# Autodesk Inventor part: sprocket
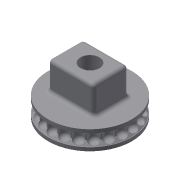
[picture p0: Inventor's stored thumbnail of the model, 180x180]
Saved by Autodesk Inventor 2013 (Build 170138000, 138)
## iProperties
Created: 2013-11
Part Number: sprocket
Material: Generic
Document SubType Name: Modeling
Designer: Jonas
Density: 1 g/cm^3
Author: Jonas
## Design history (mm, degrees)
sketch "Sketch1"
  geometry: C1 r 10.789 at (0, 0); 1 further point
  constraints: 1 centre point, 1 coincident
  dimensions: "d0" = 21.57743 diameter of C1 (computed from sprocket_N, pi)
extrude "Extrusion1" new body sketch "Sketch1" distance "d4" = 3.45 (computed from ball_diameter); taper "d5" = 0 deg
sketch "Sketch3"
  geometry: C1 r 10.789 at (0, 0) reference; C2 r 11.942 at (0, 0)
  constraints: 1 centre point, 1 coincident
  dimensions: "d12" = 23.8838 diameter of C2 (computed from pi, sprocket_N)
extrude "Extrusion2" join sketch "Sketch3" distance "d14" = 1; taper "d15" = 0 deg
chamfer "Chamfer1" distance "d66" = 1; stored, may be unused: second distance "d67" = 2, angle "d68" = 45 deg
workplane "Work Plane1"
mirror "Mirror1"
sketch "Sketch6"
  geometry: C1 r 1.375 at (0, -10.789); 1 further point
  constraints: 1 centre point, 1 vertical alignment, 1 other
  dimensions: "d23" = 2.75 diameter of C1 (computed from ball_diameter)
extrude "Extrusion4" cut sketch "Sketch6" stored distance "d24" = 10; taper "d25" = 0 deg
fillet "Fillet3" dims "d27" = 1
sketch "Sketch7"
  geometry: L1 (-7, -5)-(-7, 5); L2 (-7, 5)-(6, 5); L3 (6, 5)-(6, -5); L4 (6, -5)-(-7, -5); C1 r 11.942 at (0, 0) reference
  constraints: 8 end point, 2 parallel, 1 perpendicular
  dimensions: "d39" = 13 distance of L1.end L2.end; "d41" = 10 distance of L2.end L3.end; "d42" = 7 distance from line of C1.centre L1; "d43" = 5 distance from line of C1.centre L2
extrude "Extrusion5" join sketch "Sketch7" distance "d48" = 8; taper "d49" = 0 deg
sketch "Sketch4"
  geometry: C1 r 11.942 at (0, 0) reference; C2 r 2.7 at (0, 0)
  constraints: 1 centre point, 1 coincident
  dimensions: "d69" = 5.4 diameter of C2
extrude "Extrusion3" cut sketch "Sketch4" stored distance "d21" = 1; taper "d22" = 0 deg
sketch "Sketch8"
  geometry: L1 (0, 0)-(0, 10) reference; L2 (8, 10)-(8, 0) reference; L3 (8, 5)-(0, 5); 2 further points
  constraints: 3 midpoint, 2 end point
  dimensions: "d58" = 4 distance from line of L2 point (4, 5)
fillet "Fillet4" dims "d57" = 1
hole "Hole2" sketch "Sketch8" diameter "d59" = 3; stored, may be unused: countersink angle "d63" = 90 deg, drill point angle "d65" = 118 deg; dims "d60" = 6, "d61" = 4, "d62" = 2, "d64" = 8
body "Solid1"
pattern_circular "Circular Pattern1" dims angle "d10" = 360 deg
other parameters: "theta" = 3 deg, "sprocket_wall_clearance" = 1, "ball_diameter" = 2.45, "ball_distance" = 0.76, "frame_thickness" = 21.5, "pi" = 180 deg
